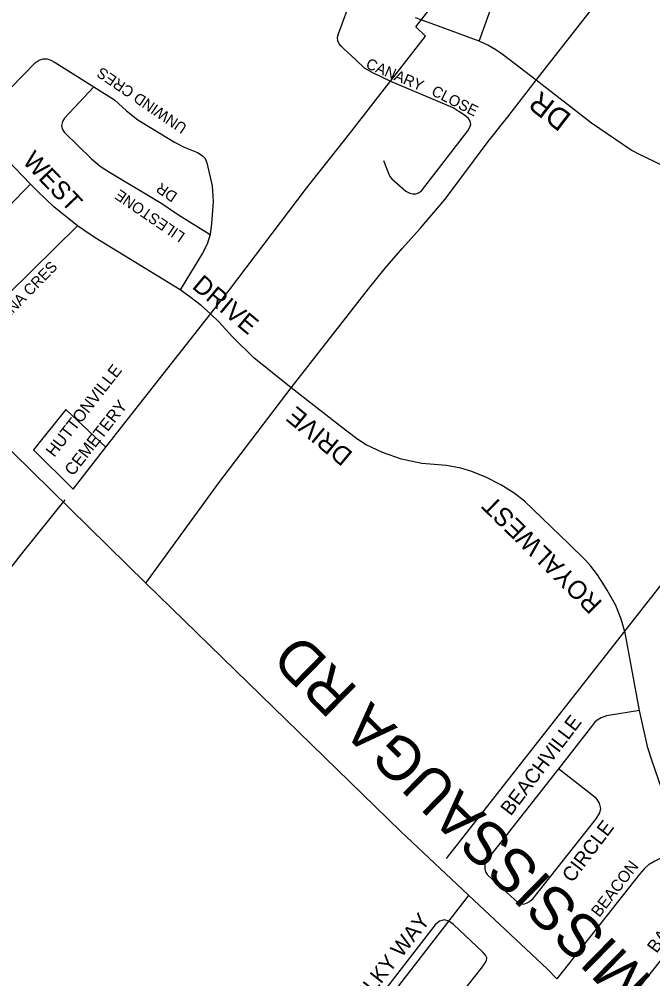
# Model space of a CAD drawing. Extents: x 586326 to 623965, y 4819854 to 4857850.
# Drawn here: x 595187 to 595922, y 4834124 to 4835238 of the extents above; entities that cross this region are included whole.
import ezdxf

# ---------------------------------------------------------------- set-up
doc = ezdxf.new("R2010")
doc.units = 0
for name, color, linetype in [('Cemeteries', 7, 'Continuous'), ('Lots_Concessions', 7, 'Continuous'), ('Major Rds and Hwys', 7, 'Continuous'), ('Major Rds Lbls', 7, 'Continuous'), ('Minor Rd Lbls', 7, 'Continuous'), ('Minor Rds', 7, 'Continuous'), ('Proposed Minor Rds', 7, 'Continuous'), ('Proposed Rd Lbls', 7, 'Continuous'), ('Proposed Secondary Rds', 7, 'Continuous'), ('Secondary Rds Lbls', 7, 'Continuous')]:
    doc.layers.add(name, color=color, linetype=linetype)

msp = doc.modelspace()

# ---------------------------------------------------------------- linework, layer by layer
at = {"layer": 'Cemeteries'}
for p, q in [((595240.7, 4834785.2), (595203.1, 4834738.4)), ((595287.2, 4834741.4), (595240.7, 4834785.2)), ((595249.4, 4834692.7), (595287.2, 4834741.4)), ((595203.1, 4834738.4), (595249.4, 4834692.7))]:
    msp.add_line(p, q, dxfattribs=at)
at = {"layer": 'Lots_Concessions'}
for p, q in [((595647.3, 4835229.4), (595765, 4835381.1)), ((595658.4, 4835218.5), (595647.3, 4835229.4)), ((595570.1, 4835104.9), (595658.4, 4835218.5)), ((595520.3, 4835042), (595570.1, 4835104.9)), ((595431, 4834924.2), (595520.3, 4835042)), ((595299.5, 4834757.2), (595431, 4834924.2)), ((595287.2, 4834741.4), (595299.5, 4834757.2)), ((595249.4, 4834692.7), (595287.2, 4834741.4)), ((595189.4, 4834617.2), (595239.8, 4834680.4)), ((595682.8, 4834264.2), (595978.2, 4834640.5)), ((595090.1, 4834490.8), (595189.4, 4834617.2)), ((595289.6, 4833682.9), (595708.5, 4834220.5))]:
    msp.add_line(p, q, dxfattribs=at)
at = {"layer": 'Major Rds and Hwys'}
for points in [[(595787.1, 4835167.2), (595981.2, 4835415.7)], [(595753.9, 4835125), (595787.1, 4835167.2)], [(595502.5, 4834810.4), (595592.3, 4834925.3), (595611.7, 4834949), (595631.9, 4834972.2), (595652.2, 4834995.4), (595681.4, 4835029.2), (595731.4, 4835096.3), (595753.9, 4835125)], [(595333.6, 4834583.5), (595157, 4834756.6), (595115.5, 4834801.5), (595035.7, 4834886.9), (594997.4, 4834929.6), (594888.4, 4835036)], [(595333.6, 4834583.5), (595418.5, 4834700), (595502.5, 4834810.4)], [(595811.1, 4834124.4), (595799.6, 4834135.8), (595714.6, 4834215.7), (595629.6, 4834295.5), (595333.6, 4834583.5)]]:
    msp.add_lwpolyline(points, dxfattribs=at)
at = {"layer": 'Minor Rds'}
for points in [[(595720.7, 4835212.8), (595743.9, 4835277.3), (595748.1, 4835286.4), (595752.2, 4835293.3)], [(595618.2, 4835166), (595597.4, 4835175.7), (595587.5, 4835181.4), (595577.5, 4835190.8), (595563.6, 4835203.6), (595560.4, 4835206.8), (595558.3, 4835209.7), (595556.8, 4835213.2), (595556.4, 4835216.8), (595557.5, 4835221.2), (595573.3, 4835264.9)], [(595134, 4835114.7), (595205.2, 4835187.4), (595209.6, 4835190.6), (595214.4, 4835192.3), (595219, 4835192.3), (595223.3, 4835190.7), (595228.2, 4835187.9), (595273.4, 4835159.5)], [(595707.5, 4835108.4), (595709.6, 4835111.9), (595711, 4835115.8), (595710.3, 4835119.6), (595708.3, 4835122.7), (595704.2, 4835126.3), (595697.9, 4835130.7), (595695.3, 4835132.3), (595690.5, 4835135.2), (595618.2, 4835166)], [(595273.4, 4835159.5), (595239.2, 4835123.3), (595236.9, 4835119.3), (595235.8, 4835114.8), (595236.4, 4835110.9), (595238.7, 4835107.1), (595270.6, 4835076), (595280.6, 4835067.7), (595291.5, 4835060.7), (595352.4, 4835024.2), (595371.6, 4835011.2), (595408.2, 4834988.1)], [(595273.4, 4835159.5), (595297.3, 4835144.4), (595311.1, 4835131.7), (595324.2, 4835121.3), (595367.1, 4835095.5), (595378.2, 4835089.5), (595393.7, 4835083.3), (595399.1, 4835080.1), (595402.7, 4835076.4), (595404.6, 4835071.5), (595410.5, 4835044.6), (595411.8, 4835026.2), (595410, 4835001), (595408.2, 4834988.1)], [(595199.7, 4835046.5), (595134, 4835114.7)], [(595609.5, 4835074.3), (595616, 4835058.3), (595617.1, 4835055.5), (595619.3, 4835052.8), (595635.7, 4835038.4), (595640.3, 4835036.4), (595643.6, 4835035.6), (595647.1, 4835035.5), (595650.4, 4835036.5), (595653.7, 4835039.1), (595707.5, 4835108.4)], [(595149.5, 4834996), (595174.6, 4835021.2), (595199.7, 4835046.5)], [(595254.1, 4834998.4), (595226.8, 4835020.5), (595207.8, 4835038.4), (595199.7, 4835046.5)], [(595254.1, 4834998.4), (595174.1, 4834919.5), (595129.9, 4834873.6), (595123.1, 4834866.8), (595117.3, 4834861.9), (595112.6, 4834860.3), (595108.1, 4834860.5)], [(595373.4, 4834923.9), (595274.8, 4834984.4), (595261.7, 4834993.4), (595254.1, 4834998.4)], [(595408.2, 4834988.1), (595404.9, 4834977.1), (595399.6, 4834966.7), (595373.4, 4834923.9)], [(595408.8, 4834896.1), (595397.8, 4834905.9), (595384.7, 4834916.1), (595373.4, 4834923.9)], [(595502.5, 4834810.4), (595459.2, 4834845), (595434.1, 4834869.5), (595418.6, 4834886.7), (595408.8, 4834896.1)], [(595906.9, 4834435.9), (595868.7, 4834429.6), (595862.3, 4834427.4), (595857.7, 4834424.5), (595854.7, 4834421.7), (595851.3, 4834417.2), (595813, 4834368)], [(595813, 4834368), (595728.8, 4834261.4), (595727.5, 4834258.1), (595727.3, 4834255), (595727.4, 4834251.8), (595728.1, 4834248.4), (595730, 4834245.6), (595746.4, 4834230.4)], [(595746.4, 4834230.4), (595765.1, 4834213.3), (595769.1, 4834212), (595772.1, 4834211), (595776.7, 4834212.4), (595779.4, 4834214), (595783.3, 4834217.5), (595856.7, 4834310), (595861.1, 4834317.1), (595862, 4834322.1), (595860.7, 4834328.3), (595857.1, 4834333.5), (595813, 4834368)], [(595943.2, 4834270.1), (595924.8, 4834261.1), (595917.4, 4834256.6), (595912.7, 4834252.5), (595907.5, 4834246.4), (595811.1, 4834124.4)], [(596044.5, 4834168.3), (595952.9, 4834052.9), (595949.4, 4834049.4), (595945.6, 4834047.9), (595942.2, 4834047.3), (595938.2, 4834047.7), (595935, 4834048.7), (595931.2, 4834051), (595897.1, 4834085.2), (595895.2, 4834088.9), (595894.7, 4834092.8), (595894.8, 4834096.2), (595896.4, 4834100), (595898.6, 4834104), (595989.9, 4834218.7)]]:
    msp.add_lwpolyline(points, dxfattribs=at)
at = {"layer": 'Proposed Minor Rds'}
msp.add_lwpolyline([(595649.8, 4834043.7), (595723.4, 4834136.6), (595727.7, 4834142.9), (595729.1, 4834145.6), (595729.6, 4834148.7), (595728.1, 4834151.7), (595725.3, 4834155.1), (595717.6, 4834162.4), (595691.1, 4834187.3), (595685.7, 4834191.3), (595680.5, 4834192.9), (595674.7, 4834191.3), (595669.5, 4834187.1), (595597.1, 4834093.4)], dxfattribs=at)
at = {"layer": 'Proposed Secondary Rds'}
for points in [[(595720.7, 4835212.8), (595673.6, 4835229.9), (595646.8, 4835239.7)], [(595787.1, 4835167.2), (595748.9, 4835196.3), (595740.2, 4835202.6), (595730.9, 4835207.9), (595720.7, 4835212.8)], [(595975.3, 4835045), (595963.7, 4835052.5), (595952, 4835058.8), (595946.1, 4835062), (595911.3, 4835079), (595910.2, 4835079.5), (595897.4, 4835086.2), (595851.3, 4835117.4), (595787.1, 4835167.2)], [(595906.9, 4834435.9), (595890.2, 4834525.9), (595885.7, 4834541.9), (595879.5, 4834557.5), (595869.4, 4834575.6), (595864.5, 4834583.6), (595858.1, 4834593.1), (595850.4, 4834603.2), (595844.3, 4834610.1), (595824.9, 4834629.4), (595773.5, 4834678.9), (595761.6, 4834688.1), (595746, 4834697.6), (595729.4, 4834706.1), (595712.3, 4834713.1), (595699.4, 4834716.9), (595682.9, 4834720.3), (595654.3, 4834722.5), (595630.4, 4834727.5), (595608.6, 4834735.2), (595589.4, 4834744.2), (595579.8, 4834750.4), (595565.6, 4834761.3), (595502.5, 4834810.4)], [(595952.7, 4834287.3), (595921.4, 4834378.3), (595916.7, 4834392.4), (595906.9, 4834435.9)]]:
    msp.add_lwpolyline(points, dxfattribs=at)

# ---------------------------------------------------------------- texts
at = {"layer": 'Cemeteries'}
for s, p in [('HUTTONVILLE', (595227.3, 4834728.9)), ('CEMETERY', (595249, 4834707.1))]:
    msp.add_text(s, height=14, rotation=52, dxfattribs=at).set_placement(p)
at = {"layer": 'Major Rds Lbls'}
msp.add_text('MISSISSAUGA RD', height=49.998, rotation=135.5246, dxfattribs=at).set_placement((595923.5, 4834124.5))
at = {"layer": 'Minor Rd Lbls'}
for s, height, rotation, p in [('CANARY', 12.64, 337.1471, (595588.1, 4835181.8)), ('UNWIND CRES', 12.644, 145.6745, (595382.5, 4835114.8)), ('CLOSE', 12.64, 333.3637, (595664.2, 4835150.6)), ('WEST', 21.28, 313.6239, (595189.3, 4835072.5)), ('DR', 12.64, 145.6745, (595371.4, 4835035.4)), ('LILESTONE', 12.64, 145.6745, (595380.2, 4834988.8)), ('VEZNA CRES', 12.64, 45.6306, (595156.4, 4834872.5)), ('DRIVE', 21.28, 320.1455, (595386.2, 4834926.6)), ('BEACHVILLE', 16.69, 52.8549, (595757.5, 4834312.6)), ('CIRCLE', 16.69, 52.8549, (595828.9, 4834235)), ('BEACON ', 13.42, 52.374, (595860.3, 4834195)), ('BALIN', 15.12, 53.8462, (595926.8, 4834153.2))]:
    msp.add_text(s, height=height, rotation=rotation, dxfattribs=at).set_placement(p)
at = {"layer": 'Proposed Rd Lbls'}
msp.add_text('MILKY WAY', height=18, rotation=51.8313, dxfattribs=at).set_placement((595581.9, 4834086.2))
at = {"layer": 'Secondary Rds Lbls'}
for s, height, rotation, p in [('DR', 25, 142.3407, (595829.4, 4835126.4)), ('DRIVE', 21.28, 140.3154, (595575.3, 4834734.5)), ('ROYALWEST ', 21.28, 135.4593, (595864.8, 4834561.3))]:
    msp.add_text(s, height=height, rotation=rotation, dxfattribs=at).set_placement(p)

doc.saveas('drawing.dxf')
